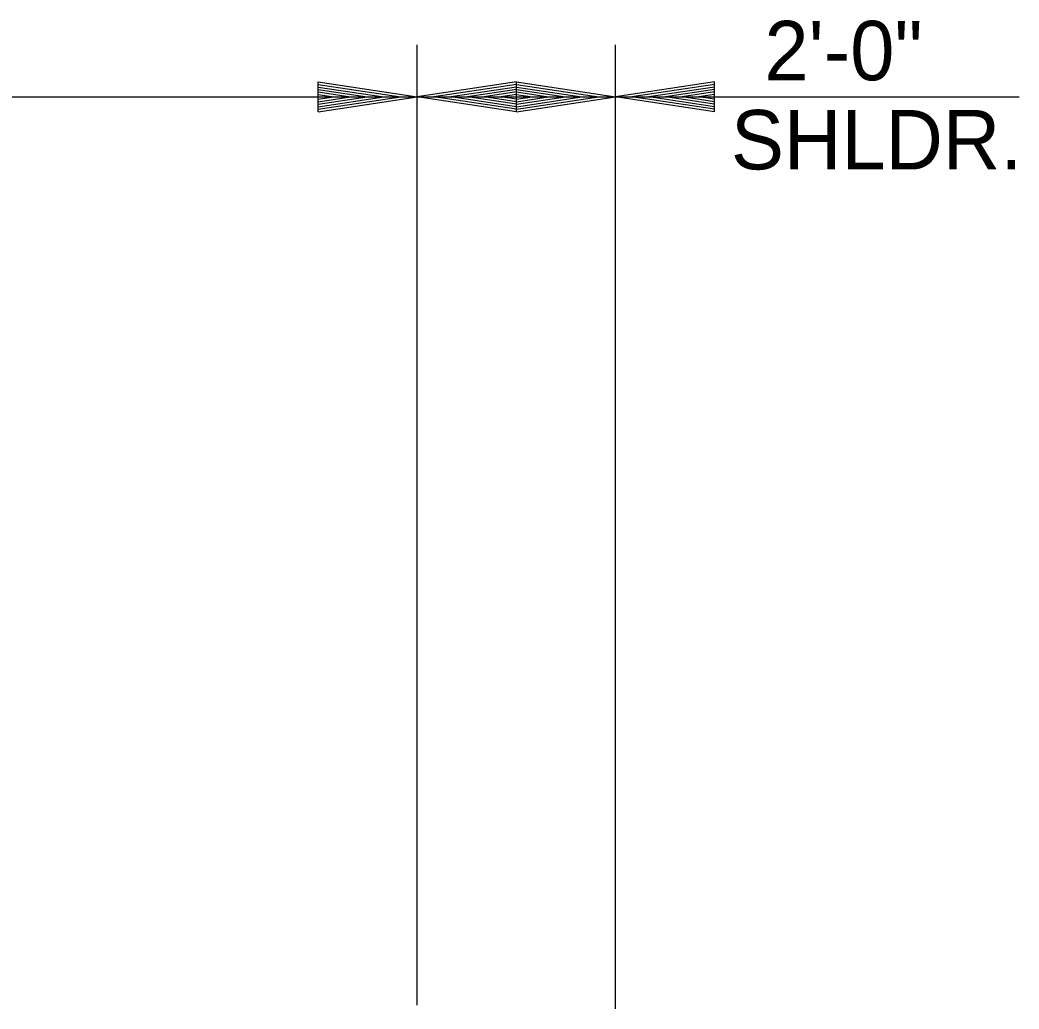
# Model space of a CAD drawing. Extents: x 2829243 to 2838161, y 467639 to 474695.
# Drawn here: x 2834134.7 to 2834235.6, y 469065.4 to 469165.3 of the extents above; entities that cross this region are included whole.
import ezdxf

# ---------------------------------------------------------------- set-up
doc = ezdxf.new("R2010")
doc.units = 0
doc.layers.add('R_Dimension', color=7, linetype='Continuous')

msp = doc.modelspace()

# ---------------------------------------------------------------- linework, layer by layer
at = {"layer": 'R_Dimension'}
for p, q in [((2834174.82, 469065.85), (2834174.82, 469162.83)), ((2834194.82, 469065.45), (2834194.82, 469162.83)), ((2834164.82, 469159.08), (2834174.82, 469157.58)), ((2834164.82, 469156.08), (2834164.82, 469159.08)), ((2834164.82, 469158.83), (2834173.15, 469157.58)), ((2834184.82, 469159.08), (2834174.82, 469157.58)), ((2834184.82, 469158.83), (2834176.49, 469157.58)), ((2834184.82, 469156.08), (2834184.82, 469159.08)), ((2834184.82, 469159.08), (2834194.82, 469157.58)), ((2834184.82, 469156.08), (2834184.82, 469159.08)), ((2834184.82, 469158.83), (2834193.15, 469157.58)), ((2834204.82, 469159.08), (2834194.82, 469157.58)), ((2834204.82, 469158.83), (2834196.49, 469157.58)), ((2834204.82, 469156.08), (2834204.82, 469159.08)), ((2834164.82, 469158.57), (2834171.43, 469157.58)), ((2834164.82, 469158.32), (2834169.77, 469157.58)), ((2834164.82, 469158.07), (2834168.07, 469157.58)), ((2834164.82, 469157.81), (2834166.4, 469157.58)), ((2834184.82, 469158.57), (2834178.21, 469157.58)), ((2834184.82, 469158.32), (2834179.88, 469157.58)), ((2834184.82, 469158.07), (2834181.57, 469157.58)), ((2834184.82, 469157.81), (2834183.24, 469157.58)), ((2834184.82, 469158.57), (2834191.43, 469157.58)), ((2834184.82, 469158.32), (2834189.77, 469157.58)), ((2834184.82, 469158.07), (2834188.07, 469157.58)), ((2834184.82, 469157.81), (2834186.4, 469157.58)), ((2834204.82, 469158.57), (2834198.21, 469157.58)), ((2834204.82, 469158.32), (2834199.88, 469157.58)), ((2834204.82, 469158.07), (2834201.57, 469157.58)), ((2834204.82, 469157.81), (2834203.24, 469157.58)), ((2834024.82, 469157.58), (2834174.82, 469157.58)), ((2834164.82, 469156.08), (2834174.82, 469157.58)), ((2834164.82, 469157.09), (2834168.07, 469157.58)), ((2834164.82, 469156.58), (2834171.43, 469157.58)), ((2834164.82, 469156.33), (2834173.15, 469157.58)), ((2834164.82, 469156.83), (2834169.77, 469157.58)), ((2834164.82, 469157.34), (2834166.4, 469157.58)), ((2834184.82, 469156.08), (2834174.82, 469157.58)), ((2834174.82, 469157.58), (2834235.58, 469157.58)), ((2834184.82, 469156.33), (2834176.49, 469157.58)), ((2834184.82, 469156.58), (2834178.21, 469157.58)), ((2834184.82, 469156.83), (2834179.88, 469157.58)), ((2834184.82, 469157.09), (2834181.57, 469157.58)), ((2834184.82, 469157.34), (2834183.24, 469157.58)), ((2834184.82, 469156.08), (2834194.82, 469157.58)), ((2834184.82, 469157.09), (2834188.07, 469157.58)), ((2834184.82, 469156.58), (2834191.43, 469157.58)), ((2834184.82, 469156.33), (2834193.15, 469157.58)), ((2834184.82, 469156.83), (2834189.77, 469157.58)), ((2834184.82, 469157.34), (2834186.4, 469157.58)), ((2834204.82, 469156.08), (2834194.82, 469157.58)), ((2834204.82, 469156.33), (2834196.49, 469157.58)), ((2834204.82, 469156.58), (2834198.21, 469157.58)), ((2834204.82, 469156.83), (2834199.88, 469157.58)), ((2834204.82, 469157.09), (2834201.57, 469157.58)), ((2834204.82, 469157.34), (2834203.24, 469157.58))]:
    msp.add_line(p, q, dxfattribs=at)

# ---------------------------------------------------------------- texts
for s, p in [('2\'-0"', (2834209.87, 469159.25)), ('SHLDR.', (2834206.49, 469150.25))]:
    msp.add_text(s, height=6, dxfattribs=at).set_placement(p)

doc.saveas('drawing.dxf')
